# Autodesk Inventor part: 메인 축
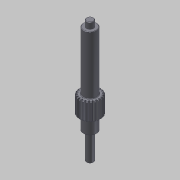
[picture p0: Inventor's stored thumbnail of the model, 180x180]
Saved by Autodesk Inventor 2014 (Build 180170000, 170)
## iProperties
Created: 2016-02
Part Number: 메인 축
Material: 강철, 연강
Document SubType Name: Modeling
Categories: <?xml version="1.0" encoding="UTF-16"?> <MemberInstance><Categories><FamilyTemplate><FamilyTemplateParameter ValueType="xs:double" Id="1" ObjectReferenceKey="da
Density: 7.86 g/cm^3
Mass: 187.503 g
Surface Area: 82.0529 cm^2
Volume: 23.8554 cm^3
Appearance: 강철
CustomPartVersion: 1
Author: mdu
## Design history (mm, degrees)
sketch "Sketch1"
  geometry: C1 r 12 at (0, 0)
  constraints: 1 centre point
  dimensions: "d0" = 24 diameter of C1 (= da_da)
extrude "Extrusion1" new body sketch "Sketch1" distance "d1" = 20 (= da_b); taper "d2" = 0 deg
workplane "Work Plane2"
feature "피치 지름" dims "d4" = 10, "d5" = 0
workplane "Work Plane8"
workplane "Work Plane9"
chamfer "모따기1" distance "d49" = 1; stored, may be unused: second distance "d50" = 2, angle "d51" = 45 deg
sketch "스케치3"
  geometry: C1 r 7.5 at (0, 0); 1 further point
  constraints: 1 centre point, 1 coincident
  dimensions: "d52" = 15 diameter of C1
extrude "돌출2" join sketch "스케치3" distance "d53" = 66; taper "d54" = 0 deg
sketch "스케치4"
  geometry: C1 r 4 at (0, 0); 1 further point
  constraints: 1 centre point, 1 coincident
  dimensions: "d55" = 8 diameter of C1
extrude "돌출3" join sketch "스케치4" distance "d56" = 7; taper "d57" = 0 deg
sketch "스케치5"
  geometry: C1 r 7.5 at (0, 0) reference; C2 r 7.5 at (0, 0) reference; 1 further point
extrude "돌출4" join sketch "스케치5" distance "d62" = 16; taper "d63" = 0 deg
sketch "스케치6"
  geometry: C1 r 4 at (0, 0); 1 further point
  constraints: 1 centre point, 1 coincident
  dimensions: "d64" = 8 diameter of C1
extrude "돌출5" join sketch "스케치6" distance "d65" = 30; taper "d66" = 0 deg
chamfer "모따기2" distance "d58" = 0.5; stored, may be unused: second distance "d59" = 2, angle "d60" = 45 deg
fillet "모깎기1" dims "d61" = 0.5
feature "스퍼 기어" dims "da_b" = 20, "da_d" = 22, "da_aw" = 31, "da_da" = 24, "da_df" = 19.5, "da_dw" = 22, angle "da_beta" = 0 deg, "da_lefttooth" = 0, "da_righttooth" = 0
sketch "스케치7" dims "d68" = 18
  geometry: C1 r 0.25 at (0, -9); 2 further points
  constraints: 2 vertical alignment, 1 centre point, 1 coincident, 2 other
  dimensions: "d67" = 0.5 diameter of C1
extrude "돌출6" join sketch "스케치7" distance "d69" = 0.3; taper "d70" = 0 deg
body "Solid1"
sketch "Sketch2"
  geometry: C1 r 12 at (0, 0) reference; C2 r 11 at (0, 0)
  constraints: 1 centre point, 1 coincident
  dimensions: "d3" = 22 diameter of C2 (= da_dw)
body "Srf1"
node "투영된 루프1"
other parameters: "d16" = 31 (= da_aw), "d17" = 0, "d34" = 1.428 (computed from da_z), "d39" = 0, "d41" = 0, "d43" = 31 (= da_aw), "d46" = 31 (= da_aw), "d47" = 0, "d48" = 0
